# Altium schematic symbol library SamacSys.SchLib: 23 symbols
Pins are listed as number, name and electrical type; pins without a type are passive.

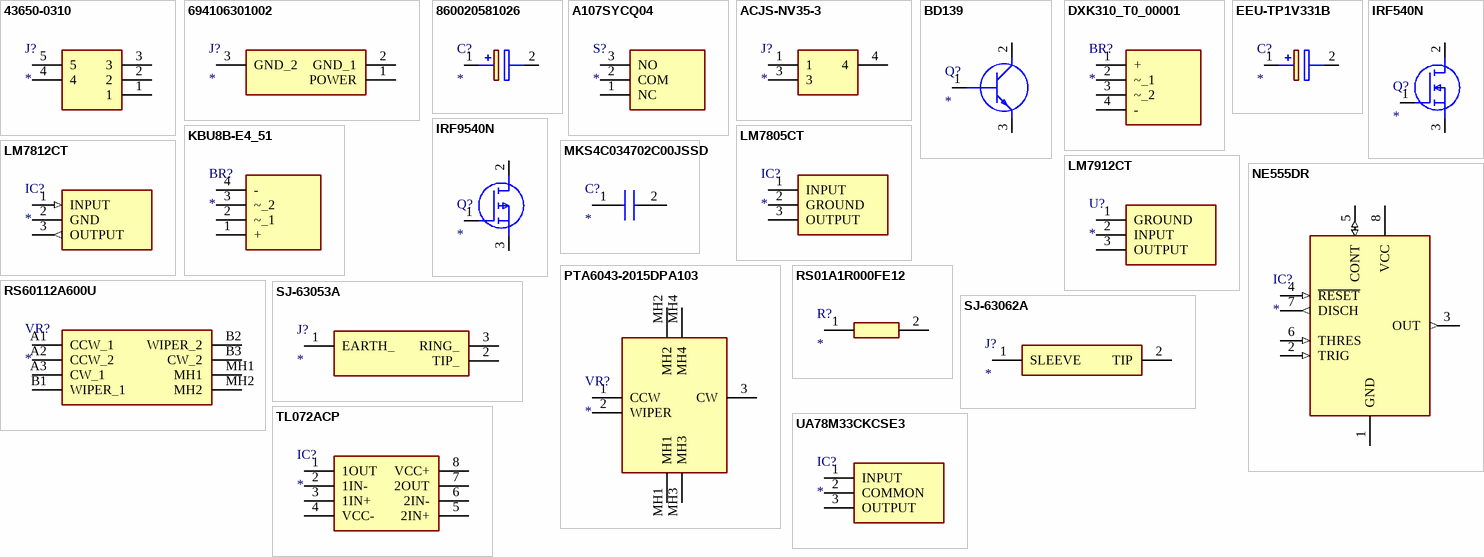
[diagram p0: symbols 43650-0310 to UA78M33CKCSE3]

## 43650-0310
designator J?
Connector; Manufacturer_Name: Molex; Manufacturer_Part_Number: 43650-0310
footprint 43650-03YY_091011
pins: 1, 2, 3, 4, 5

## 694106301002
designator J?
Connector; Manufacturer_Name: Wurth Elektronik; Manufacturer_Part_Number: 694106301002
footprint 694106301002_1
pins: 1 POWER, 2 GND_1, 3 GND_2

## 860020581026
designator C?
Capacitor Polarised; Manufacturer_Name: Wurth Elektronik; Manufacturer_Part_Number: 860020581026
footprint CAPPRD750W82D1800H3750
pins: 1 +, 2 -

## A107SYCQ04
designator S?
Switch; Manufacturer_Name: TE Connectivity; Manufacturer_Part_Number: A107SYCQ04
footprint A107SYCQ04
pins: 1 NC, 2 COM, 3 NO

## ACJS-NV35-3
designator J?
Connector; Manufacturer_Name: Amphenol; Manufacturer_Part_Number: ACJS-NV35-3
footprint ACJSNV353
pins: 1, 3, 4

## BD139
designator Q?
Transistor BJT NPN; Manufacturer_Name: STMicroelectronics; Manufacturer_Part_Number: BD139
footprint TO254P290X760X1320-3P
pins: 1 B, 2 C, 3 E

## DXK310_T0_00001
designator BR?
Bridge Rectifier; Manufacturer_Name: PANJIT; Manufacturer_Part_Number: DXK310_T0_00001
footprint DXK310_T0_00001
pins: 1 +, 2 ~_1, 3 ~_2, 4 -

## EEU-TP1V331B
designator C?
Capacitor Polarised; Manufacturer_Name: Panasonic; Manufacturer_Part_Number: EEU-TP1V331B
footprint CAPPRD500W65D1000H2200
pins: 1 +, 2 -

## IRF540N
designator Q?
MOSFET (N-Channel); Manufacturer_Name: Infineon; Manufacturer_Part_Number: IRF540N
footprint TO254P469X1042X1967-3P
pins: 1 G, 2 D, 3 S

## IRF9540N
designator Q?
MOSFET (P-Channel); Manufacturer_Name: Infineon; Manufacturer_Part_Number: IRF9540N
footprint TO254P469X1042X1967-3P
pins: 1 G, 2 D, 3 S

## KBU8B-E4_51
designator BR?
Bridge Rectifier; Manufacturer_Name: Vishay; Manufacturer_Part_Number: KBU8B-E4/51
footprint KBU8BE451
pins: 1 +, 2 ~_1, 3 ~_2, 4 -

## LM7805CT
designator IC?
Integrated Circuit; Manufacturer_Name: Texas Instruments; Manufacturer_Part_Number: LM7805CT
footprint TO254P470X1028X1955-3P
pins: 1 INPUT, 2 GROUND, 3 OUTPUT

## LM7812CT
designator IC?
Integrated Circuit; Manufacturer_Name: Texas Instruments; Manufacturer_Part_Number: LM7812CT
footprint TO254P470X1028X1955-3P
pins: 1 INPUT (in), 2 GND (power), 3 OUTPUT (out)

## LM7912CT
designator U?
Undefined or Miscellaneous; Manufacturer_Name: Texas Instruments; Manufacturer_Part_Number: LM7912CT
footprint TO254P470X1028X1955-3P
pins: 1 GROUND (power), 2 INPUT (power), 3 OUTPUT (power)

## MKS4C034702C00JSSD
designator C?
Capacitor; Manufacturer_Name: WIMA; Manufacturer_Part_Number: MKS4C034702C00JSSD
footprint MKS4C034702C00JSSD
pins: 1, 2

## NE555DR
designator IC?
Integrated Circuit; Manufacturer_Name: Texas Instruments; Manufacturer_Part_Number: NE555DR
footprint SOIC127P600X175-8N
pins: 1 GND (power), 2 TRIG (in), 3 OUT (out), 4 ~{RESET} (in), 5 CONT (io), 6 THRES (in), 7 DISCH (out), 8 VCC (power)

## PTA6043-2015DPA103
designator VR?
Variable Resistor; Manufacturer_Name: Bourns; Manufacturer_Part_Number: PTA6043-2015DPA103; Description: Slide Potentiometers 15MM SHAFT NO DET 60MM STRK SNG AUD
footprint PTA60432015DPA103
pins: 1 CCW, 2 WIPER, 3 CW, MH1, MH2, MH3, MH4

## RS01A1R000FE12
designator R?
Resistor; Manufacturer_Name: Vishay; Manufacturer_Part_Number: RS01A1R000FE12
footprint RESAD1987W56L1031D239
pins: 1, 2

## RS60112A600U
designator VR?
Variable Resistor; Manufacturer_Name: ALPS Electric; Manufacturer_Part_Number: RS60112A600U
footprint RS60112A600U
pins: A1 CCW_1, A2 CCW_2, A3 CW_1, B1 WIPER_1, B2 WIPER_2, B3 CW_2, MH1, MH2

## SJ-63053A
designator J?
Connector; Manufacturer_Name: Same Sky; Manufacturer_Part_Number: SJ-63053A
footprint SJ63053A
pins: 1 EARTH_, 2 TIP_, 3 RING_

## SJ-63062A
designator J?
Connector; Manufacturer_Name: Same Sky; Manufacturer_Part_Number: SJ-63062A
footprint SJ63062A
pins: 1 SLEEVE, 2 TIP

## TL072ACP
designator IC?
Integrated Circuit; Manufacturer_Name: Texas Instruments; Manufacturer_Part_Number: TL072ACP
footprint DIP794W53P254L959H508Q8N
pins: 1 1OUT, 2 1IN-, 3 1IN+, 4 VCC-, 5 2IN+, 6 2IN-, 7 2OUT, 8 VCC+

## UA78M33CKCSE3
designator IC?
Integrated Circuit; Manufacturer_Name: Texas Instruments; Manufacturer_Part_Number: UA78M33CKCSE3
footprint TO254P470X1016X1965-3P
pins: 1 INPUT, 2 COMMON, 3 OUTPUT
